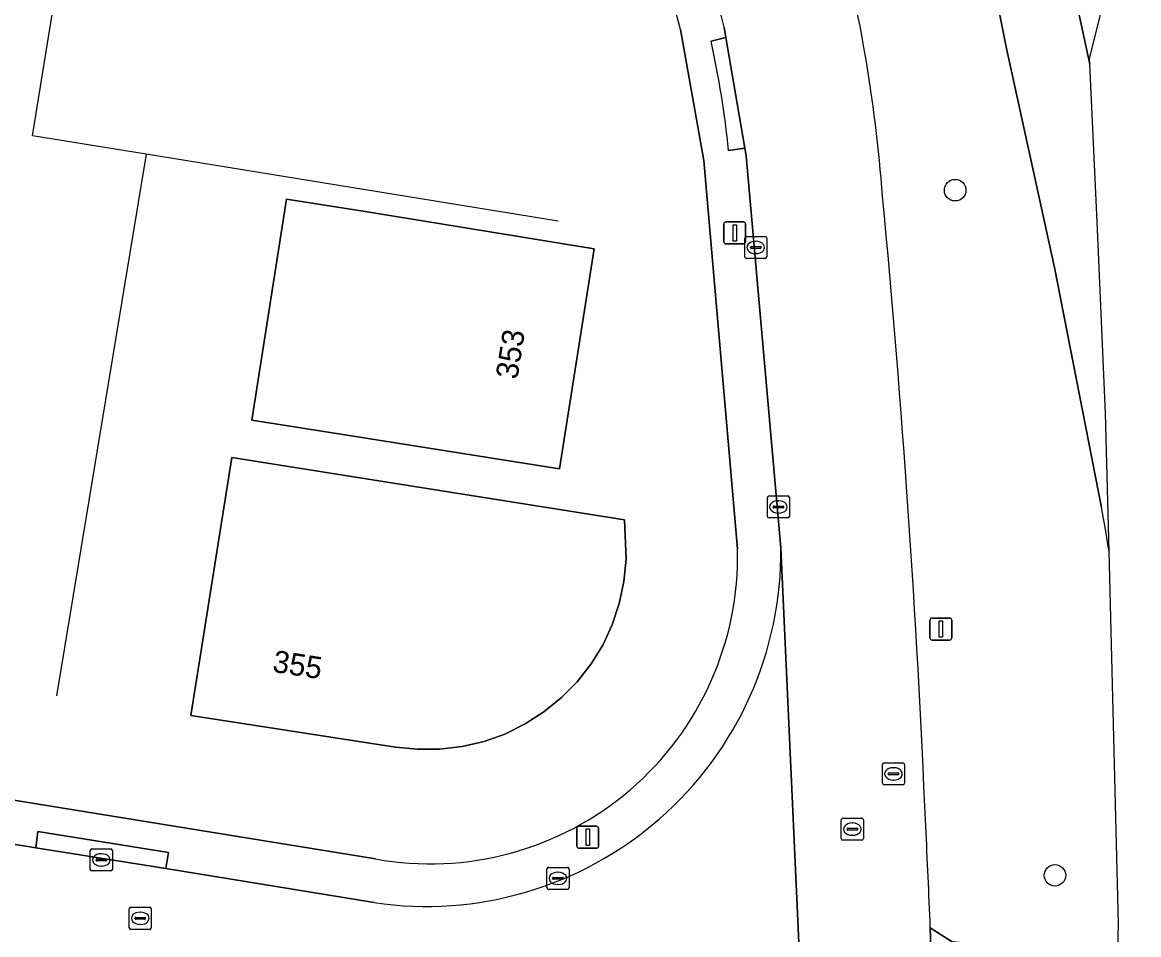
# Model space of a CAD drawing. Extents: x 154324 to 155744, y 382937 to 384188.
# Drawn here: x 155347.8 to 155398.4, y 383380.4 to 383421.7 of the extents above; entities that cross this region are included whole.
import ezdxf

# ---------------------------------------------------------------- set-up
doc = ezdxf.new("R2010")
doc.units = 0
for name, color, linetype in [('IMGEO_Berm_groen', 7, 'Continuous'), ('IMGEO_Boom', 7, 'Continuous'), ('IMGEO_Erf', 7, 'Continuous'), ('IMGEO_Fietspad_gesloten', 7, 'Continuous'), ('IMGEO_Hek', 7, 'Continuous'), ('IMGEO_Kolk', 7, 'Continuous'), ('IMGEO_Lichtmast', 7, 'Continuous'), ('IMGEO_Pand', 7, 'Continuous'), ('IMGEO_Pand_nummerreeks', 7, 'Continuous'), ('IMGEO_Rijbaan_lokaal_gesloten', 7, 'Continuous'), ('IMGEO_Rijbaan_lokaal_open', 7, 'Continuous'), ('IMGEO_Rioolput', 7, 'Continuous'), ('IMGEO_Voetpad_halfverhard', 7, 'Continuous'), ('IMGEO_Voetpad_open', 7, 'Continuous')]:
    doc.layers.add(name, color=color, linetype=linetype)

msp = doc.modelspace()

# ---------------------------------------------------------------- linework, layer by layer
at = {"layer": 'IMGEO_Berm_groen'}
for points in [[(155395.459, 383423.267), (155396.197, 383419.838), (155396.185, 383420.089), (155398.413, 383429.086), (155397.699, 383432.608), (155397.566, 383432.755)], [(155396.734, 383399.741), (155394.603, 383410.617), (155392.42, 383420.546), (155391.049, 383427.415)], [(155388.962, 383380.68), (155389.952, 383380.04), (155391.104, 383379.937), (155397.46, 383379.674), (155397.493, 383380.862), (155397.072, 383397.736)]]:
    msp.add_lwpolyline(points, dxfattribs=at)
for centre, radius, start, end in [((155318.229, 383408.711), 68.76, 4.27157, 15.2271), ((154843.279, 383362.211), 545.965, 2.42265, 5.42556), ((155282.089, 383379.399), 116.435, 9.06123, 10.0617), ((155046.983, 383367.704), 342.225, 2.17293, 2.94535)]:
    msp.add_arc(centre, radius, start, end, dxfattribs=at)
at = {"layer": 'IMGEO_Boom'}
for centre in [(155390.09, 383414.125), (155394.616, 383383.052)]:
    msp.add_circle(centre, 0.489, dxfattribs=at)
at = {"layer": 'IMGEO_Erf'}
for points in [[(155338.312, 383461.713), (155333.894, 383463.145), (155328.096, 383422.22), (155326.654, 383413.134), (155323.037, 383390.342), (155343.85, 383387.039), (155363.801, 383383.796)], [(155380.219, 383397.854), (155378.698, 383415.475), (155377.629, 383421.408)]]:
    msp.add_lwpolyline(points, dxfattribs=at)
for points in [[(155373.726, 383411.47), (155372.155, 383401.491), (155361.747, 383403.13), (155358.19, 383403.69), (155359.772, 383413.719), (155363.328, 383413.159)], [(155375.089, 383399.177), (155375.169, 383397.39), (155375.062, 383396.372), (155374.853, 383395.378), (155374.537, 383394.413), (155374.109, 383393.498), (155373.58, 383392.642), (155372.947, 383391.834), (155372.244, 383391.114), (155371.443, 383390.465), (155370.598, 383389.917), (155369.674, 383389.463), (155368.725, 383389.125), (155367.735, 383388.897), (155366.71, 383388.776), (155365.709, 383388.768), (155364.71, 383388.866), (155355.426, 383390.304), (155357.286, 383402.004)]]:
    msp.add_lwpolyline(points, close=True, dxfattribs=at)
for centre, radius, start, end in [((155326.36, 383409.367), 52.663, 13.2166, 54.1334), ((155366.279, 383397.518), 13.944, 259.7627, 1.3812)]:
    msp.add_arc(centre, radius, start, end, dxfattribs=at)
at = {"layer": 'IMGEO_Fietspad_gesloten'}
for points in [[(155391.049, 383427.415), (155392.42, 383420.546), (155394.603, 383410.617), (155396.734, 383399.741)], [(155396.197, 383419.838), (155395.459, 383423.267)], [(155397.072, 383397.736), (155396.915, 383404.013), (155396.529, 383412.695), (155396.197, 383419.838)]]:
    msp.add_lwpolyline(points, dxfattribs=at)
msp.add_arc((155282.089, 383379.399), 116.435, 9.06123, 10.0617, dxfattribs=at)
at = {"layer": 'IMGEO_Hek'}
for points in [[(155353.397, 383415.758), (155348.254, 383416.592), (155350.587, 383431.051)], [(155353.397, 383415.758), (155349.344, 383391.187)], [(155372.086, 383412.727), (155353.397, 383415.758)]]:
    msp.add_lwpolyline(points, dxfattribs=at)
at = {"layer": 'IMGEO_Kolk'}
for p, q in [((155380.547, 383411.103), (155380.547, 383411.955)), ((155380.622, 383412.029), (155381.474, 383412.029)), ((155381.035, 383411.809), (155381.06, 383411.809)), ((155381.548, 383411.955), (155381.548, 383411.103)), ((155380.806, 383411.523), (155380.806, 383411.535)), ((155381.244, 383411.486), (155380.846, 383411.486)), ((155380.849, 383411.572), (155381.247, 383411.572)), ((155381.058, 383411.249), (155381.033, 383411.249)), ((155381.29, 383411.535), (155381.29, 383411.523)), ((155381.474, 383411.029), (155380.622, 383411.029)), ((155381.574, 383399.334), (155381.574, 383400.186)), ((155381.649, 383400.26), (155382.501, 383400.26)), ((155382.062, 383400.04), (155382.087, 383400.04)), ((155382.575, 383400.186), (155382.575, 383399.334)), ((155381.833, 383399.754), (155381.833, 383399.766)), ((155382.271, 383399.717), (155381.873, 383399.717)), ((155381.876, 383399.803), (155382.274, 383399.803)), ((155382.317, 383399.766), (155382.317, 383399.754)), ((155382.501, 383399.26), (155381.649, 383399.26)), ((155382.085, 383399.48), (155382.06, 383399.48)), ((155350.871, 383383.325), (155350.871, 383384.177)), ((155350.946, 383384.251), (155351.798, 383384.251)), ((155351.359, 383384.031), (155351.384, 383384.031)), ((155351.872, 383384.177), (155351.872, 383383.325)), ((155351.13, 383383.745), (155351.13, 383383.757)), ((155351.568, 383383.708), (155351.17, 383383.708)), ((155351.173, 383383.794), (155351.571, 383383.794)), ((155351.382, 383383.471), (155351.357, 383383.471)), ((155351.614, 383383.757), (155351.614, 383383.745)), ((155371.578, 383382.49), (155371.578, 383383.342)), ((155371.653, 383383.416), (155372.505, 383383.416)), ((155372.579, 383383.342), (155372.579, 383382.49)), ((155351.798, 383383.251), (155350.946, 383383.251)), ((155371.837, 383382.91), (155371.837, 383382.922)), ((155372.275, 383382.873), (155371.877, 383382.873)), ((155371.88, 383382.959), (155372.278, 383382.959)), ((155372.066, 383383.196), (155372.091, 383383.196)), ((155372.321, 383382.922), (155372.321, 383382.91)), ((155372.505, 383382.416), (155371.653, 383382.416)), ((155372.089, 383382.636), (155372.064, 383382.636))]:
    msp.add_line(p, q, dxfattribs=at)
for points in [[(155380.547, 383411.103), (155380.547, 383411.955)], [(155380.622, 383412.029), (155381.474, 383412.029)], [(155381.548, 383411.955), (155381.548, 383411.103)], [(155381.474, 383411.029), (155380.622, 383411.029)], [(155381.574, 383399.334), (155381.574, 383400.186)], [(155381.649, 383400.26), (155382.501, 383400.26)], [(155382.575, 383400.186), (155382.575, 383399.334)], [(155382.501, 383399.26), (155381.649, 383399.26)], [(155350.871, 383383.325), (155350.871, 383384.177)], [(155350.946, 383384.251), (155351.798, 383384.251)], [(155351.872, 383384.177), (155351.872, 383383.325)], [(155371.578, 383382.49), (155371.578, 383383.342)], [(155371.653, 383383.416), (155372.505, 383383.416)], [(155372.579, 383383.342), (155372.579, 383382.49)], [(155351.798, 383383.251), (155350.946, 383383.251)], [(155372.505, 383382.416), (155371.653, 383382.416)]]:
    msp.add_lwpolyline(points, dxfattribs=at)
for centre, radius, start, end in [((155380.624, 383411.953), 0.0765, 91.552, 178.448), ((155380.624, 383411.953), 0.0765, 91.552, 178.448), ((155381.472, 383411.953), 0.0765, 1.552, 88.448), ((155381.472, 383411.953), 0.0765, 1.552, 88.448), ((155380.846, 383411.532), 0.0403, 85.8775, 175.7526), ((155380.843, 383411.522), 0.0366, 178.938, 274.7102), ((155381.247, 383411.529), 0.043, 264.8664, 352.4533), ((155381.251, 383411.534), 0.0386, 1.7309, 96.639), ((155380.624, 383411.105), 0.0765, 181.552, 268.448), ((155380.624, 383411.105), 0.0765, 181.552, 268.448), ((155381.472, 383411.105), 0.0765, 271.552, 358.448), ((155381.472, 383411.105), 0.0765, 271.552, 358.448), ((155381.651, 383400.184), 0.0765, 91.552, 178.448), ((155381.651, 383400.184), 0.0765, 91.552, 178.448), ((155382.499, 383400.184), 0.0765, 1.552, 88.448), ((155382.499, 383400.184), 0.0765, 1.552, 88.448), ((155381.873, 383399.763), 0.0403, 85.8775, 175.7526), ((155381.87, 383399.753), 0.0366, 178.938, 274.7102), ((155382.274, 383399.76), 0.043, 264.8664, 352.4533), ((155382.278, 383399.765), 0.0386, 1.7309, 96.639), ((155381.651, 383399.336), 0.0765, 181.552, 268.448), ((155381.651, 383399.336), 0.0765, 181.552, 268.448), ((155382.499, 383399.336), 0.0765, 271.552, 358.448), ((155382.499, 383399.336), 0.0765, 271.552, 358.448), ((155350.948, 383384.175), 0.0765, 91.552, 178.448), ((155350.948, 383384.175), 0.0765, 91.552, 178.448), ((155351.796, 383384.175), 0.0765, 1.552, 88.448), ((155351.796, 383384.175), 0.0765, 1.552, 88.448), ((155350.948, 383383.327), 0.0765, 181.552, 268.448), ((155350.948, 383383.327), 0.0765, 181.552, 268.448), ((155351.17, 383383.754), 0.0403, 85.8775, 175.7526), ((155351.167, 383383.744), 0.0366, 178.938, 274.7102), ((155351.571, 383383.751), 0.043, 264.8664, 352.4533), ((155351.575, 383383.756), 0.0386, 1.7309, 96.639), ((155351.796, 383383.327), 0.0765, 271.552, 358.448), ((155351.796, 383383.327), 0.0765, 271.552, 358.448), ((155371.655, 383383.34), 0.0765, 91.552, 178.448), ((155371.655, 383383.34), 0.0765, 91.552, 178.448), ((155372.503, 383383.34), 0.0765, 1.552, 88.448), ((155372.503, 383383.34), 0.0765, 1.552, 88.448), ((155371.877, 383382.919), 0.0403, 85.8775, 175.7526), ((155371.874, 383382.909), 0.0366, 178.938, 274.7102), ((155372.278, 383382.916), 0.043, 264.8664, 352.4533), ((155372.282, 383382.921), 0.0386, 1.7309, 96.639), ((155371.655, 383382.492), 0.0765, 181.552, 268.448), ((155371.655, 383382.492), 0.0765, 181.552, 268.448), ((155372.503, 383382.492), 0.0765, 271.552, 358.448), ((155372.503, 383382.492), 0.0765, 271.552, 358.448)]:
    msp.add_arc(centre, radius, start, end, dxfattribs=at)
for centre, major_axis, ratio, start_param, end_param in [((155381.034, 383411.529), (-0.387, 0.002), 0.722429, 4.712389, 7.853982), ((155381.059, 383411.529), (-0.39, 0.002), 0.717154, 1.570796, 4.712389), ((155382.061, 383399.76), (-0.387, 0.002), 0.722429, 4.712389, 7.853982), ((155382.086, 383399.76), (-0.39, 0.002), 0.717154, 1.570796, 4.712389), ((155351.358, 383383.751), (-0.387, 0.002), 0.722429, 4.712389, 7.853982), ((155351.383, 383383.751), (-0.39, 0.002), 0.717154, 1.570796, 4.712389), ((155372.065, 383382.916), (-0.387, 0.002), 0.722429, 4.712389, 7.853982), ((155372.09, 383382.916), (-0.39, 0.002), 0.717154, 1.570796, 4.712389)]:
    msp.add_ellipse(centre, major_axis=major_axis, ratio=ratio, start_param=start_param, end_param=end_param, dxfattribs=at)
at = {"layer": 'IMGEO_Lichtmast'}
for p, q in [((155379.698, 383412.687), (155380.488, 383412.687)), ((155380.488, 383412.687), (155379.698, 383412.687)), ((155379.598, 383411.787), (155379.598, 383412.587)), ((155379.598, 383412.587), (155379.598, 383411.787)), ((155380.588, 383412.587), (155380.588, 383411.787)), ((155380.588, 383411.787), (155380.588, 383412.587)), ((155380.488, 383411.687), (155379.698, 383411.687)), ((155379.698, 383411.687), (155380.488, 383411.687)), ((155388.945, 383393.823), (155388.945, 383394.623)), ((155388.945, 383394.623), (155388.945, 383393.823)), ((155389.045, 383394.723), (155389.835, 383394.723)), ((155389.835, 383394.723), (155389.045, 383394.723)), ((155389.935, 383394.623), (155389.935, 383393.823)), ((155389.935, 383393.823), (155389.935, 383394.623)), ((155389.835, 383393.723), (155389.045, 383393.723)), ((155389.045, 383393.723), (155389.835, 383393.723)), ((155372.933, 383384.383), (155372.933, 383385.183)), ((155372.933, 383385.183), (155372.933, 383384.383)), ((155373.033, 383385.283), (155373.823, 383385.283)), ((155373.823, 383385.283), (155373.033, 383385.283)), ((155373.923, 383385.183), (155373.923, 383384.383)), ((155373.923, 383384.383), (155373.923, 383385.183)), ((155373.823, 383384.283), (155373.033, 383384.283)), ((155373.033, 383384.283), (155373.823, 383384.283))]:
    msp.add_line(p, q, dxfattribs=at)
for points in [[(155380.018, 383412.562), (155380.168, 383412.562), (155380.168, 383411.812), (155380.018, 383411.812), (155380.018, 383412.562)], [(155389.365, 383394.598), (155389.515, 383394.598), (155389.515, 383393.848), (155389.365, 383393.848), (155389.365, 383394.598)], [(155373.353, 383385.158), (155373.503, 383385.158), (155373.503, 383384.408), (155373.353, 383384.408), (155373.353, 383385.158)]]:
    msp.add_lwpolyline(points, dxfattribs=at)
for centre, start, end in [((155379.698, 383412.587), 90, 180), ((155379.698, 383412.587), 90, 180), ((155380.488, 383412.587), 0, 90), ((155380.488, 383412.587), 360, 90), ((155379.698, 383411.787), 180, 270), ((155379.698, 383411.787), 180, 270), ((155380.488, 383411.787), 270, 0), ((155380.488, 383411.787), 270, 0), ((155389.045, 383394.623), 90, 180), ((155389.045, 383394.623), 90, 180), ((155389.835, 383394.623), 0, 90), ((155389.835, 383394.623), 360, 90), ((155389.045, 383393.823), 180, 270), ((155389.045, 383393.823), 180, 270), ((155389.835, 383393.823), 270, 0), ((155389.835, 383393.823), 270, 0), ((155373.033, 383385.183), 90, 180), ((155373.033, 383385.183), 90, 180), ((155373.823, 383385.183), 0, 90), ((155373.823, 383385.183), 360, 90), ((155373.033, 383384.383), 180, 270), ((155373.033, 383384.383), 180, 270), ((155373.823, 383384.383), 270, 0), ((155373.823, 383384.383), 270, 0)]:
    msp.add_arc(centre, 0.1, start, end, dxfattribs=at)
at = {"layer": 'IMGEO_Pand'}
for points in [[(155372.155, 383401.491), (155373.726, 383411.47), (155363.328, 383413.159), (155359.772, 383413.719), (155358.19, 383403.69), (155361.747, 383403.13)], [(155366.71, 383388.776), (155367.735, 383388.897), (155368.725, 383389.125), (155369.674, 383389.463), (155370.598, 383389.917), (155371.443, 383390.465), (155372.244, 383391.114), (155372.947, 383391.834), (155373.58, 383392.642), (155374.109, 383393.498), (155374.537, 383394.413), (155374.853, 383395.378), (155375.062, 383396.372), (155375.169, 383397.39), (155375.089, 383399.177), (155357.286, 383402.004), (155355.426, 383390.304), (155364.71, 383388.866), (155365.709, 383388.768)]]:
    msp.add_lwpolyline(points, close=True, dxfattribs=at)
at = {"layer": 'IMGEO_Rijbaan_lokaal_gesloten'}
for points in [[(155383.12, 383377.352), (155382.189, 383397.912)], [(155363.743, 383381.814), (155354.292, 383383.36), (155348.398, 383384.302), (155344.042, 383385.007), (155322.727, 383388.39)]]:
    msp.add_lwpolyline(points, dxfattribs=at)
msp.add_arc((155366.094, 383397.738), 16.096, 261.6031, 0.62, dxfattribs=at)
at = {"layer": 'IMGEO_Rijbaan_lokaal_open'}
for points in [[(155379.61, 383421.518), (155379.69, 383421.052), (155380.297, 383417.532), (155380.555, 383416.035), (155380.615, 383415.683), (155382.189, 383397.912), (155383.12, 383377.352), (155383.264, 383374.318), (155383.19, 383366.215), (155383.081, 383354.275), (155381.974, 383334.287)], [(155389.068, 383377.555), (155388.962, 383380.68)]]:
    msp.add_lwpolyline(points, dxfattribs=at)
for centre, radius, start, end in [((155326.335, 383409.358), 54.645, 12.8574, 53.718), ((155318.229, 383408.711), 68.76, 4.27157, 15.2271), ((154843.279, 383362.211), 545.965, 2.42265, 5.42556), ((155046.983, 383367.704), 342.225, 2.17293, 2.94535)]:
    msp.add_arc(centre, radius, start, end, dxfattribs=at)
at = {"layer": 'IMGEO_Rioolput'}
for p, q in [((155386.793, 383387.228), (155386.793, 383388.08)), ((155386.868, 383388.154), (155387.72, 383388.154)), ((155387.281, 383387.934), (155387.306, 383387.934)), ((155387.794, 383388.08), (155387.794, 383387.228)), ((155387.052, 383387.648), (155387.052, 383387.66)), ((155387.49, 383387.611), (155387.092, 383387.611)), ((155387.095, 383387.697), (155387.493, 383387.697)), ((155387.304, 383387.374), (155387.279, 383387.374)), ((155387.536, 383387.66), (155387.536, 383387.648)), ((155387.72, 383387.154), (155386.868, 383387.154)), ((155384.928, 383384.723), (155384.928, 383385.575)), ((155385.003, 383385.649), (155385.855, 383385.649)), ((155385.416, 383385.429), (155385.441, 383385.429)), ((155385.929, 383385.575), (155385.929, 383384.723)), ((155385.187, 383385.143), (155385.187, 383385.155)), ((155385.625, 383385.106), (155385.227, 383385.106)), ((155385.23, 383385.192), (155385.628, 383385.192)), ((155385.439, 383384.869), (155385.414, 383384.869)), ((155385.671, 383385.155), (155385.671, 383385.143)), ((155385.855, 383384.649), (155385.003, 383384.649)), ((155352.637, 383380.678), (155352.637, 383381.53)), ((155352.712, 383381.604), (155353.564, 383381.604)), ((155353.125, 383381.384), (155353.15, 383381.384)), ((155353.638, 383381.53), (155353.638, 383380.678)), ((155352.896, 383381.098), (155352.896, 383381.11)), ((155353.334, 383381.061), (155352.936, 383381.061)), ((155352.939, 383381.147), (155353.337, 383381.147)), ((155353.148, 383380.824), (155353.123, 383380.824)), ((155353.38, 383381.11), (155353.38, 383381.098)), ((155353.564, 383380.604), (155352.712, 383380.604))]:
    msp.add_line(p, q, dxfattribs=at)
for points in [[(155386.793, 383387.228), (155386.793, 383388.08)], [(155386.868, 383388.154), (155387.72, 383388.154)], [(155387.794, 383388.08), (155387.794, 383387.228)], [(155387.72, 383387.154), (155386.868, 383387.154)], [(155384.928, 383384.723), (155384.928, 383385.575)], [(155385.003, 383385.649), (155385.855, 383385.649)], [(155385.929, 383385.575), (155385.929, 383384.723)], [(155385.855, 383384.649), (155385.003, 383384.649)], [(155352.637, 383380.678), (155352.637, 383381.53)], [(155352.712, 383381.604), (155353.564, 383381.604)], [(155353.638, 383381.53), (155353.638, 383380.678)], [(155353.564, 383380.604), (155352.712, 383380.604)]]:
    msp.add_lwpolyline(points, dxfattribs=at)
for centre, radius, start, end in [((155386.87, 383388.078), 0.0765, 91.552, 178.448), ((155386.87, 383388.078), 0.0765, 91.552, 178.448), ((155387.718, 383388.078), 0.0765, 1.552, 88.448), ((155387.718, 383388.078), 0.0765, 1.552, 88.448), ((155387.092, 383387.657), 0.0403, 85.8775, 175.7526), ((155387.089, 383387.647), 0.0366, 178.938, 274.7102), ((155387.493, 383387.654), 0.043, 264.8664, 352.4533), ((155387.497, 383387.659), 0.0386, 1.7309, 96.639), ((155386.87, 383387.23), 0.0765, 181.552, 268.448), ((155386.87, 383387.23), 0.0765, 181.552, 268.448), ((155387.718, 383387.23), 0.0765, 271.552, 358.448), ((155387.718, 383387.23), 0.0765, 271.552, 358.448), ((155385.005, 383385.573), 0.0765, 91.552, 178.448), ((155385.005, 383385.573), 0.0765, 91.552, 178.448), ((155385.853, 383385.573), 0.0765, 1.552, 88.448), ((155385.853, 383385.573), 0.0765, 1.552, 88.448), ((155385.227, 383385.152), 0.0403, 85.8775, 175.7526), ((155385.224, 383385.142), 0.0366, 178.938, 274.7102), ((155385.628, 383385.149), 0.043, 264.8664, 352.4533), ((155385.632, 383385.154), 0.0386, 1.7309, 96.639), ((155385.005, 383384.725), 0.0765, 181.552, 268.448), ((155385.005, 383384.725), 0.0765, 181.552, 268.448), ((155385.853, 383384.725), 0.0765, 271.552, 358.448), ((155385.853, 383384.725), 0.0765, 271.552, 358.448), ((155352.714, 383381.528), 0.0765, 91.552, 178.448), ((155352.714, 383381.528), 0.0765, 91.552, 178.448), ((155353.562, 383381.528), 0.0765, 1.552, 88.448), ((155353.562, 383381.528), 0.0765, 1.552, 88.448), ((155352.936, 383381.107), 0.0403, 85.8775, 175.7526), ((155352.933, 383381.097), 0.0366, 178.938, 274.7102), ((155353.337, 383381.104), 0.043, 264.8664, 352.4533), ((155353.341, 383381.109), 0.0386, 1.7309, 96.639), ((155352.714, 383380.68), 0.0765, 181.552, 268.448), ((155352.714, 383380.68), 0.0765, 181.552, 268.448), ((155353.562, 383380.68), 0.0765, 271.552, 358.448), ((155353.562, 383380.68), 0.0765, 271.552, 358.448)]:
    msp.add_arc(centre, radius, start, end, dxfattribs=at)
for centre, major_axis, ratio, start_param, end_param in [((155387.28, 383387.654), (-0.387, 0.002), 0.722429, 4.712389, 7.853982), ((155387.305, 383387.654), (-0.39, 0.002), 0.717154, 1.570796, 4.712389), ((155385.415, 383385.149), (-0.387, 0.002), 0.722429, 4.712389, 7.853982), ((155385.44, 383385.149), (-0.39, 0.002), 0.717154, 1.570796, 4.712389), ((155353.124, 383381.104), (-0.387, 0.002), 0.722429, 4.712389, 7.853982), ((155353.149, 383381.104), (-0.39, 0.002), 0.717154, 1.570796, 4.712389)]:
    msp.add_ellipse(centre, major_axis=major_axis, ratio=ratio, start_param=start_param, end_param=end_param, dxfattribs=at)
at = {"layer": 'IMGEO_Voetpad_halfverhard'}
msp.add_lwpolyline([(155397.412, 383377.951), (155397.46, 383379.674), (155391.104, 383379.937), (155389.952, 383380.04), (155388.962, 383380.68), (155389.068, 383377.555), (155390.399, 383378.047)], close=True, dxfattribs=at)
at = {"layer": 'IMGEO_Voetpad_open'}
for points in [[(155377.629, 383421.408), (155378.698, 383415.475), (155380.219, 383397.854)], [(155379.024, 383420.888), (155379.69, 383421.052), (155379.61, 383421.518)], [(155379.69, 383421.052), (155379.024, 383420.888)], [(155379.819, 383415.926), (155380.555, 383416.035), (155380.297, 383417.532), (155379.69, 383421.052)], [(155382.189, 383397.912), (155380.615, 383415.683), (155380.555, 383416.035), (155379.819, 383415.926)], [(155363.801, 383383.796), (155343.85, 383387.039), (155323.037, 383390.342), (155322.727, 383388.39), (155344.042, 383385.007), (155348.398, 383384.302), (155348.489, 383385.035), (155354.424, 383384.089), (155354.292, 383383.36), (155363.743, 383381.814)]]:
    msp.add_lwpolyline(points, dxfattribs=at)
msp.add_lwpolyline([(155354.292, 383383.36), (155354.424, 383384.089), (155348.489, 383385.035), (155348.398, 383384.302)], close=True, dxfattribs=at)
for centre, radius, start, end in [((155326.335, 383409.358), 54.645, 12.8574, 53.718), ((155326.36, 383409.367), 52.663, 13.2166, 54.1334), ((155333.621, 383411.069), 46.453, 6.0018, 12.2031), ((155333.621, 383411.069), 46.453, 6.0018, 12.2031), ((155366.094, 383397.738), 16.096, 261.6031, 0.62), ((155366.279, 383397.518), 13.944, 259.7627, 1.3812)]:
    msp.add_arc(centre, radius, start, end, dxfattribs=at)

# ---------------------------------------------------------------- texts
at = {"layer": 'IMGEO_Pand_nummerreeks'}
for s, rotation, p in [('353', 81.05, (155370.237, 383405.514)), ('355', 351.1928, (155359.095, 383392.286))]:
    msp.add_text(s, height=1, rotation=rotation, dxfattribs=at).set_placement(p)

doc.saveas('drawing.dxf')
